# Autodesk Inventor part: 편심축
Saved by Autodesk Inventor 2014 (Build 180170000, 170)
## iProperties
Created: 2026-03
Part Number: 편심축
Material: 강철, 탄소
Document SubType Name: Modeling
Designer: dg
Density: 7.87 g/cm^3
Appearance: 반연마
Mass: 134.759 g
Surface Area: 51.5783 cm^2
Volume: 17.1232 cm^3
Author: jhkim
Creation Date: 2025-06-27
Sending System: Autodesk Inventor 2026
Preprocessor: ST-DEVELOPER v20.1
Author: dg
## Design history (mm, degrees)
node "편심축1"
node "솔리드1"
node "기준1"
